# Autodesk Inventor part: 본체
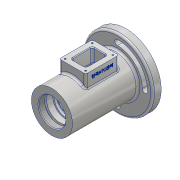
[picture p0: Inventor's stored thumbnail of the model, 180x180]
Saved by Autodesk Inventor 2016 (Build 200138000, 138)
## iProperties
Created: 2017-05
Part Number: 본체
Material: 알루미늄 6061
Document SubType Name: Modeling
Designer: KSEW
Density: 2.7 g/cm^3
Appearance: 알루미늄 - 평지
Mass: 717.463 g
Surface Area: 630.64 cm^2
Volume: 265.727 cm^3
Author: KSEW
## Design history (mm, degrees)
sketch "스케치1"
  geometry: C1 r 31 at (0, 0); 1 further point
  constraints: 1 centre point, 1 coincident
  dimensions: "d0" = 62 diameter of C1
extrude "돌출1" new body sketch "스케치1" stored distance "d1" = 115; taper "d2" = 0 deg
node "작업 평면1"
sketch "스케치2"
  geometry: L1 (-78.678, -1.5)-(78.004, -1.5); L2 (-31, -57.5)-(31, -57.5) reference; L3 (20, 23.5)-(-20, 23.5); L4 (-20, 23.5)-(-20, -26.5); L5 (-20, -26.5)-(20, -26.5); L6 (20, -26.5)-(20, 23.5); L7 (20, 23.5)-(-20, -26.5); L8 (-20, 23.5)-(20, -26.5); 2 further points
  constraints: 14 end point, 2 horizontal, 2 midpoint, 2 parallel, 1 perpendicular, 1 point on line
  dimensions: "d4" = 56 distance between parallel lines of L1 L2; "d5" = 50 distance of L3.end L4.end; "d6" = 40 distance of L3.start L3.end
extrude "돌출2" join sketch "스케치2" stored distance "d7" = 115; taper "d8" = 0 deg
node "작업 평면2"
sketch "스케치3"
  geometry: C1 r 53 at (0, 0); C2 r 31 at (0, 0) reference; 1 further point
  constraints: 1 centre point, 1 coincident
  dimensions: "d10" = 106 diameter of C1
extrude "돌출3" join sketch "스케치3" distance "d11" = 13; taper "d12" = 0 deg
sketch "스케치4"
  geometry: C1 r 53 at (0, 0) reference; A1 r 4 centre (0, 41.5) between (0, 37.5) and (0, 45.5); A2 r 4 centre (-41.5, 0) between (-45.5, 0) and (-37.5, 0); A3 r 4 centre (0, -41.5) between (0, -37.5) and (0, -45.5); A4 r 4 centre (41.5, 0) between (45.5, 0) and (37.5, 0); A5 r 37.5 centre (0, 0) between (0, -37.5) and (37.5, 0); A6 r 37.5 centre (0, 0) between (0, 37.5) and (-37.5, 0); A7 r 45.5 centre (0, 0) between (0, -45.5) and (45.5, 0); A8 r 45.5 centre (0, 0) between (0, 45.5) and (-45.5, 0)
  constraints: 16 point on circle, 8 centre point, 3 equal radius, 2 coincident
  dimensions: "d16" = 8 diameter of A4
extrude "돌출4" cut sketch "스케치4" stored distance "d17" = 50; taper "d18" = 0 deg
sketch "스케치5"
  geometry: L1 (20, 23.5)-(-20, 23.5) reference; L2 (-20, 23.5)-(-20, -26.5) reference; L3 (-20, -26.5)-(20, -26.5) reference; L4 (20, -26.5)-(20, 23.5) reference; L5 (-11, -17.5)-(-11, 14.5); L6 (-11, 14.5)-(11, 14.5); L7 (11, 14.5)-(11, -17.5); L8 (11, -17.5)-(-11, -17.5); 1 further point
  constraints: 8 end point, 3 other
  dimensions: "d19" = 32 distance of L6.end L7.end
extrude "돌출5" cut sketch "스케치5" distance "d20" = 50; taper "d21" = 0 deg
sketch "스케치6"
  geometry: C1 r 31 at (0, 0) reference; 1 further point
  constraints: 1 coincident
hole "구멍1" sketch "스케치6" at (0, 0) diameter "d22" = 40.376; stored, may be unused: countersink angle "d26" = 90 deg, drill point angle "d28" = 118 deg; dims "d23" = 8.5, "d24" = 4, "d25" = 2, "d27" = 9
sketch "스케치7"
  geometry: L1 (-48.5, 0)-(-48.5, 24); L2 (-48.5, 24)-(-45.5, 24); L3 (-45.5, 24)-(-45.5, 20); L4 (-45.5, 20)-(-36.5, 20); L5 (-36.5, 20)-(-36.5, 17.5); L6 (-36.5, 17.5)-(-33.25, 17.5); L7 (-33.25, 17.5)-(-33.25, 18.5); L8 (-33.25, 18.5)-(-31.5, 18.5); L9 (-31.5, 18.5)-(-31.5, 17.5); L10 (-57.5, 31)-(-57.5, -31) reference; L11 (57.5, -31)-(57.5, 31) reference; L12 (57.5, 22)-(45.318, 16.779); L13 (43.5, 14.022)-(43.5, 13.5); L14 (42.8, 12.5)-(36.5, 12.5); L15 (36.2, 12.2)-(36.2, 10); L16 (36.2, 10)-(33.5, 10); L17 (28.5, 16.5)-(30.5, 16.5); L18 (33.5, 13.5)-(33.5, 10); L19 (28.5, 17.2)-(28.5, 16.5); L20 (-1.5, 88.119)-(-1.5, -70.588); L21 (-20.5, 23)-(-20.5, 18.5); L22 (17.5, 23)-(17.5, 18.5); L23 (-17.5, 26)-(14.5, 26); L24 (-31.5, 17.5)-(-21.5, 17.5); L25 (18.5, 17.5)-(28.2, 17.5); L26 (-21.5, 17.5)-(-20.5, 18.5); L27 (18.5, 17.5)-(17.5, 18.5); L28 (57.5, 22)-(57.5, 0); L29 (-48.5, 0)-(57.5, 0); L30 (42.8, 12.5)-(43.5, 12.904); L31 (43.5, 13.5)-(43.5, 12.904); A1 r 0.3 centre (36.5, 12.2) between (36.5, 12.5) and (36.2, 12.2); A2 r 3 centre (-17.5, 23) between (-17.5, 26) and (-20.5, 23); A3 r 3 centre (14.5, 23) between (17.5, 23) and (14.5, 26); A4 r 3 centre (46.5, 14.022) between (45.318, 16.779) and (43.5, 14.022); A5 r 3 centre (30.5, 13.5) between (33.5, 13.5) and (30.5, 16.5); A6 r 0.3 centre (28.2, 17.2) between (28.5, 17.2) and (28.2, 17.5); 9 further points
  constraints: 58 end point, 19 point on line, 12 point on circle, 12 tangent, 11 perpendicular, 6 centre point, 5 vertical, 3 horizontal, 3 parallel, 1 equal radius
  dimensions: "d29" = 9 distance between parallel lines of L1 L10; "d30" = 3 distance of L1.end L2.end; "d31" = 21 distance from line of L5.end L10; "d32" = 26 distance between parallel lines of L10 L9; "d35" = 1.75 distance of L7.end L8.end; "d36" = 60 distance of L9.end point (28.5, 17.5); "d39" = 2.7 distance of L15.end L16.end; "d43" = 0.3 radius of A1; "d51" = 56 distance between parallel lines of L20 L10; "d52" = 38 diameter of L22 L20; "d53" = 38 diameter of L21 L20; "d55" = 3 radius of A2; "d56" = 1 distance of L24.end point (-20.5, 17.5); "d57" = 45 deg angle of L24 L26; "d58" = 1 distance of L25.start point (17.5, 17.5) (= d56); "d59" = 45 deg angle of L25 L27 (= d57); "d62" = 3 radius of A4; "d63" = 3 radius of A5; "d64" = 0.3 radius of A6; "d90" = 30 deg angle of L14 L30
revolve "회전1" stored, may be unused: angle "d65" = 90 deg
fillet "모깎기1" dims "d66" = 3
sketch "스케치8"
  geometry: L1 (11, -17.5)-(-11, -17.5) reference; L2 (-11, -17.5)-(-11, 14.5) reference; L3 (-11, 14.5)-(11, 14.5) reference; L4 (11, 14.5)-(11, -17.5) reference; L5 (-15.5, 19)-(-15.5, -22); L6 (-15.5, -22)-(15.5, -22); L7 (15.5, -22)-(15.5, 19); L8 (15.5, 19)-(-15.5, 19); 5 further points
  constraints: 8 end point, 4 coincident, 3 other
  dimensions: "d67" = 41 distance of L5.start L5.end
hole "구멍2" sketch "스케치8" at (-15.5, -22), (15.5, -22), (15.5, 19), (-15.5, 19) diameter "d68" = 2.459; stored, may be unused: countersink angle "d72" = 90 deg, drill point angle "d74" = 118 deg; dims "d69" = 6, "d70" = 4, "d71" = 2, "d73" = 8
fillet "모깎기2" dims "d75" = 3
chamfer "모따기1" distance "d76" = 1; stored, may be unused: second distance "d77" = 2, angle "d78" = 45 deg
fillet "모깎기3" dims "d79" = 3
fillet "모깎기4" dims "d80" = 3
chamfer "모따기2" distance "d81" = 1; stored, may be unused: second distance "d82" = 2, angle "d83" = 45 deg
sketch "스케치9"
  geometry: L1 (0, 0)-(0, 44) reference; L2 (13, -34)-(75, -34) reference; 2 further points
  constraints: 1 other
  dimensions: "d84" = 56 distance from line of point (8, 22) L2; "d85" = 8 distance from line of point (8, 22) L1
feature "엠보싱1" sketch "스케치9" dims "d86" = 0.5, "d87" = 0
fillet "모깎기5" dims "d88" = 3
node "솔리드1"
other parameters: "d3" = 44, "d9" = -3, "d14" = 91, "d41" = 25, "d44" = 32, "d45" = 44, "d46" = 33, "d47" = 35, "d48" = 37, "d50" = 48, "d54" = 52
